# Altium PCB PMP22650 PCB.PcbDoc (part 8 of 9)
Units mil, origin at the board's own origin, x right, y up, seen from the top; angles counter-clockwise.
Board outline 11311 x 5233 mil, 8 copper layers (Layer 1, Layer 2, Layer 3, Layer 4, Layer 5, Layer 6, Layer 7, Layer 8), stack 88.6 mil thick; 633 components, 410 nets, 2503 pads, 1993 vias.
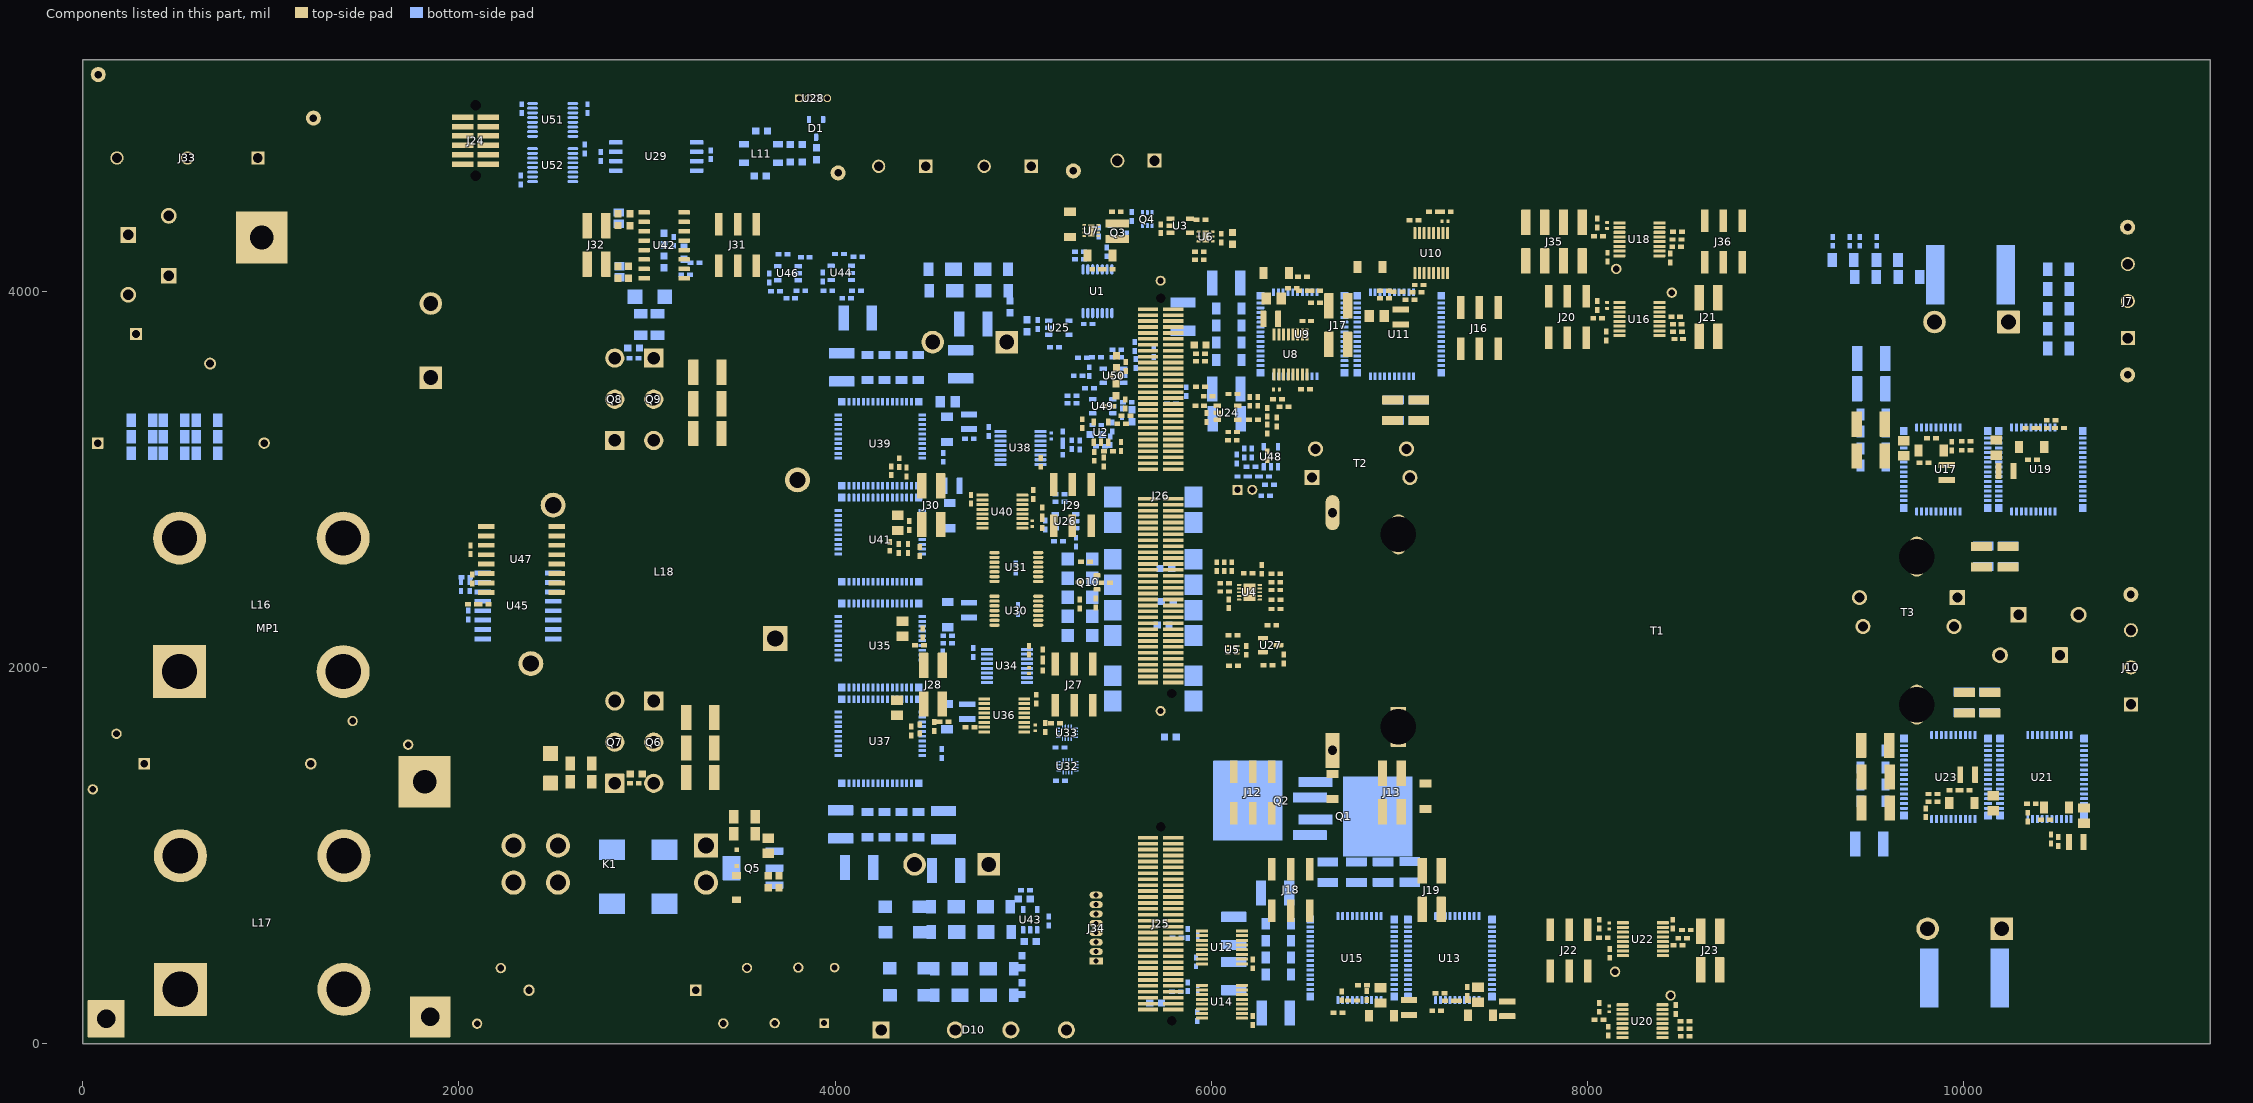
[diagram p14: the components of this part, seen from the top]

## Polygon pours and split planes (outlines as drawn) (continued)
NetL3_2 on Layer 8 "NONET_L-01_P-001" (solid, remove dead copper, pour order 249): 6232.27,4022 6282.27,4022 6282.27,3958.6 6232.27,3958.6
PGND on Layer 8 "NONET_L-01_P-001" (solid, remove dead copper, pour order 251): 5782,3997.6 5925,3997.6 5925,3912.6 5782,3912.6
NetL5_2 on Layer 8 "NONET_L-01_P-001" (solid, remove dead copper, pour order 255): 7469,203 7518.27,203 7518.27,274.6 7469,274.6
ISO_12V_L_B on Layer 8 "NONET_L-01_P-001" (solid, remove dead copper, pour order 16): 7375,135.4 7410.85,135.4 7410.85,185 7375,185
VNEG_L_B on Layer 8 "NONET_L-01_P-001" (solid, remove dead copper, pour order 17): 7446,324.6 7446,281.6 7513.27,281.6 7513.27,324.6 7468.27,324.6
NetL6_2 on Layer 8 "NONET_L-01_P-001" (solid, remove dead copper, pour order 256): 6938.27,274.6 6938.27,201 6993.27,201 6993.27,274.6
VNEG_H_B on Layer 8 "NONET_L-01_P-001" (solid, remove dead copper, pour order 257): 6927,324.6 6993.27,324.6 6993.27,281.6 6927,281.6
VNEG_H_PFC_1 on Layer 8 "NONET_L-01_P-001" (solid, remove dead copper, pour order 263): 4373.27,1852.6 4373.27,1792.6 4413.27,1792.6 4413.27,1852.6
ISO_12V_H_PFC_1 on Layer 8 "NONET_L-01_P-001" (solid, remove dead copper, pour order 266): 4563.27,1697.6 4648.27,1697.6 4648.27,1652.6 4563.27,1652.6
VNEG_H_PFC_1 on Layer 8 "NONET_L-01_P-001" (solid, remove dead copper, pour order 15): 4373.27,1852.6 4373.27,1787.6 4413.27,1787.6 4413.27,1852.6
VNEG_L_PFC_1 on Layer 8 "NONET_L-01_P-001" (solid, remove dead copper, pour order 269): 4373.27,2367.6 4373.27,2292.6 4413.27,2292.6 4413.27,2367.6
NetL12_2 on Layer 8 "NONET_L-01_P-001" (solid, remove dead copper, pour order 270): 4423.27,2362.6 4423.27,2302.6 4468.27,2302.6 4468.27,2362.6
NetL12_2 on Layer 8 "NONET_L-01_P-001" (solid, remove dead copper, pour order 276): 4668.27,2302.6 4753.27,2302.6 4753.27,2252.6 4668.27,2252.6
ISO_12V_L_PFC_1 on Layer 8 "NONET_L-01_P-001" (solid, remove dead copper, pour order 278): 4568.27,2257.6 4628.27,2257.6 4628.27,2192.6 4568.27,2192.6
NetL14_2 on Layer 8 "NONET_L-01_P-001" (solid, remove dead copper, pour order 280): 4686.27,3302.6 4668.27,3284.6 4668.27,3252.6 4754.27,3252.6 4754.27,3283.6 4735.27,3302.6
NetL14_2 on Layer 8 "NONET_L-01_P-001" (solid, remove dead copper, pour order 281): 4423.27,3437.6 4498.27,3437.6 4498.27,3392.6 4423.27,3392.6
VNEG_L_PFC_2 on Layer 8 "NONET_L-01_P-001" (solid, remove dead copper, pour order 283): 4373.27,3437.6 4373.27,3362.6 4413.27,3362.6 4413.27,3437.6
VNEG_L_PFC_2 on Layer 8 "NONET_L-01_P-001" (solid, remove dead copper, pour order 284): 4513.27,3447.6 4583.27,3447.6 4583.27,3382.6 4513.27,3382.6
IPRI_SENSE on Layer 8 "NONET_L-01_P-001" (solid, remove dead copper, pour order 289): 3978.27,3927.6 4073.27,3927.6 4073.27,3792.6 3978.27,3792.6
AC_N on Layer 8 "NONET_L-01_P-001" (solid, remove dead copper, pour order 290): 2810.27,4181 2895.27,4181 2895.27,4109.6 2810.27,4109.6
ISO_12V_H_RECT on Layer 8 "NONET_L-01_P-001" (solid, remove dead copper, pour order 291): 2815.27,4099.6 2895.27,4099.6 2895.27,4034.6 2815.27,4034.6
IPRI_SENSE on Layer 8 "NONET_L-01_P-001" (solid, remove dead copper, pour order 294): 2920,4444.6 2920,4394.6 2815.27,4394.6 2815.27,4444.6
PGND on Layer 8 "NONET_L-01_P-001" (solid, remove dead copper, pour order 299): 1973.27,2497.6 2023.27,2497.6 2023.27,2442.6 1973.27,2442.6
ISO_ETAS_GND on Layer 8 "NONET_L-01_P-001" (solid, remove dead copper, pour order 306): 2308.27,4547.6 2308.27,4592.6 2423.27,4592.6 2423.27,4547.6
ISO_3.3V on Layer 8 "NONET_L-01_P-001" (solid, remove dead copper, pour order 309): 2423.27,4832.6 2358.27,4832.6 2354.53,4971.16 2263.27,4971.16 2263.27,4832.6 2218.27,4787.6 2218.27,4757.6 2298.27,4677.6 2298.27,4602.6 2423.27,4602.6 2423.27,4622.6 2363.27,4622.6 2358.27,4627.6 2358.27,4747.6 2423.27,4747.6
ISO_ETAS_GND on Layer 8 "NONET_L-01_P-001" (solid, remove dead copper, pour order 310): 2308.27,4969.61 2308.27,5042.6 2423.27,5042.6 2423.27,4987.6 2359.15,4987.6 2359.15,4969.61
3V3_PRI on Layer 8 "NONET_L-01_P-001" (solid, remove dead copper, pour order 311): 2568.27,4832.6 2638.27,4832.6 2638.27,4937.6 2673.27,4972.6 2733.27,4972.6 2733.27,4762.6 2638.27,4762.6 2628.27,4752.6 2568.27,4752.6
PGND on Layer 8 "NONET_L-01_P-001" (solid, remove dead copper, pour order 313): 22 vertices, not listed, extent 2568.27,4542.6 2873.27,4817.6
3V3_PRI on Layer 8 "NONET_L-01_P-001" (solid, remove dead copper, pour order 324): 2798.27,4662.6 2873.27,4662.6 2873.27,4607.6 2868.27,4602.6 2798.27,4602.6
PGND on Layer 8 "NONET_L-01_P-001" (solid, remove dead copper, pour order 349): 2573.27,5042.6 2703.27,5042.6 2703.27,4982.6 2648.27,4982.6 2638.27,4992.6 2573.27,4992.6
5V_H_B on Layer 1 "NONET_L-01_P-001" (solid, pour order 522): 6107,276 6109,274 6189,274 6194,279 6194,295 6133,295 6128,300 6107,300
SW_B on Layer 1 "Layer 1-HS_GND_B" (solid, remove dead copper, pour order 454): 6132.25,153 6198.4,150.83 6259.49,78 7098,78 7098,250 7098,340 6551.81,337.61 6549.85,201.24 6498,153 6297.71,153 6250.62,192 6250.62,337.61 6132.25,340
5V_H_B on Layer 1 "NONET_L-01_P-001" (solid, pour order 521): 6170,145 6171,144 6194,144 6222,116 6222,83 6173,83 6152,104 6152,145
DCLINK on Layer 1 "NONET_L-01_P-001" (solid, pour order 514): 6035,113 6072,113 6072,92 6035,92
PGND on Layer 1 "NONET_L-01_P-001" (solid, pour order 513): 6121,623 6122,624 6255,624 6255,434 6121.99,434
SW_A on Layer 1 "NONET_L-01_P-001" (solid, pour order 400): 23 vertices, not listed, extent 6683,3651 7289,4139
PGND on Layer 1 "NONET_L-01_P-001" (solid, pour order 462): 7194,822 7490.93,822 7490.93,372.24 7639,228 7639,142 7575,78 7156.49,78 7156.49,385 6546,385 6546,632 7194,632
SW_C on Layer 1 "NONET_L-01_P-001" (solid, pour order 504): 10137,3160 10137,3105 10220.79,3105 10230,3084 10230,2999 10289,2999 10294,3004 10294,3126 10260,3160
5V_H_D on Layer 1 "NONET_L-01_P-001" (solid, pour order 434): 8584,750 8467,633 8369,633.78 8369,599 8487,599 8584,696 9428,696 9863,1131 9863,1317 9731,1317 9731,1090 9391,750
IPRI_SENSE on Layer 1 "NONET_L-01_P-001" (solid, remove dead copper, pour order 186): 4496.59,3118.88 4496.59,2896.41 4477.88,2877.7 4390.56,2877.7 4299.27,2968.98 4248.18,2968.98 4248.18,3013.16 4275.61,3040.6 4400.92,3040.6 4400.92,3045.84 4437.98,3082.91 4437.98,3118.88
TTPLPFC_SW1 on Layer 1 "Layer 1-HS_GND_PFC_1" (solid, pour order 465): 4425,1498 4826,1498 4826,1666 4726,1666 4713,1679 4713,1699 4474,1699 4474,1727.27 4440.13,1727.27 4413.83,1777.6 4295,1777.6 4295,1628
SGND on Layer 1 "NONET_L-01_P-001" (solid, pour order 425): 9841,3258 9869,3258 9869,3236 9897,3236 9920,3213 9920,3171 9951,3171 9951,3123 9951,3068 9886,3068 9832,3122 9832,3208.4
3V3_PRI on Layer 1 "NONET_L-01_P-001" (solid, remove dead copper, pour order 175): 25 vertices, not listed, extent 5990.27,3388.93 6540,4307.91
VNEG_H_PFC_2 on Layer 1 "NONET_L-01_P-001" (solid, remove dead copper, pour order 287): 4297,2848.6 4297,2780 4360,2780 4406,2826 4406,2848.6
TTPLPFC_SW2 on Layer 1 "NONET_L-01_P-001" (solid, pour order 403): 4299,2757 4404,2757 4404,2691 4299,2691
ISO_12V_H_PFC_2 on Layer 1 "NONET_L-01_P-001" (solid, remove dead copper, pour order 292): 4436,2827.6 4483.27,2827.6 4513.27,2797.6 4513.27,2757.6 4483.27,2727.6 4483.27,2692.6 4436,2692.6
LC_GATE on Layer 1 "NONET_L-01_P-001" (solid, remove dead copper, pour order 114): 7031.27,1520 6401.94,1520 6401.94,1114 6586.74,1114 6586.74,1164.6 6487.28,1164.6 6487.28,1318.71 6512.5,1339 6698,1339 7031.27,1339
3V3_PRI on Layer 1 "NONET_L-01_P-001" (solid, remove dead copper, pour order 217): 6344,2524.47 6189,2524.47 6189,2492 6158.36,2475.16 6158.36,2430.28 6140.71,2430.28 6120,2450.99 6120,2512.56 6096.99,2535.57 5980.2,2535.57 5980.2,3167.7 6344,3167.7
5V_L_D on Layer 1 "NONET_L-01_P-001" (solid, pour order 436): 8506,253 8840,253 8966,379 9421,379 9825,783 10009,783 10368,1142 10448,1142 10448,998 10136,686 9791,686 9370,265 8962,265 8830,133 8506,135.01
DCLINK on Layer 1 "NONET_L-01_P-001" (solid, remove dead copper, pour order 329): 3175.66,3642.6 3310,3642.6 3310,3177.6 3181.86,3177.6 3088.18,3287.6 2765.55,3287.6 2765.55,3571.6 3093.64,3571.6
PGND on Layer 1 "NONET_L-01_P-001" (solid, remove dead copper, pour order 166): 5952.26,4230.6 5952.26,4150.6 5990.27,4150.6 5990.27,4260.31 5989.27,4261.31 5990.27,4262.31 5990.27,4303.25 6020.1,4303.25 6032.68,4290.67 6140.59,4290.67 7052,4290.67 7135,4290.67 7135,4431 5952.26,4431
TTPLPFC_SW1 on Layer 1 "NONET_L-01_P-001" (solid, pour order 451): 4543,1875 4704,1875 4762,1817 4824,1817 4824,1802 4762,1802 4697,1737 4544,1737
ISO_12V_H_PFC_1 on Layer 1 "NONET_L-01_P-001" (solid, remove dead copper, pour order 188): 4443,1883.01 4518.26,1883.01 4518.26,1751.5 4443,1752.51
TTPLPFC_SW2 on Layer 1 "NONET_L-01_P-001" (solid, remove dead copper, pour order 293): 4528.27,2666 4528.27,2707.6 4528.27,2762.6 4528.27,2868 4688.67,2868 4723.02,2902.35 4812,2902.35 4812,2666
5V_PRI on Layer 1 "NONET_L-01_P-001" (solid, remove dead copper, pour order 147): 5424.27,4324.44 5424.27,4147.6 5944.27,4147.6 5944.27,4324.44
NetL4_2 on Layer 1 "NONET_L-01_P-001" (solid, pour order 1): 6963,3923 6963,3884 6964,3884 6976,3872 7041,3872 7054,3885 7054,3923
5V_H_A on Layer 1 "NONET_L-01_P-001" (solid, pour order 383): 7019,4133 7095,4133 7095,3979 7095,3940 7019,3940 7019,3955
SW_A on Layer 1 "NONET_L-01_P-001" (solid, pour order 396): 6746,4169 6746,4053 6879,4053.01 6879,4169
TTPLPFC_SW2 on Layer 1 "NONET_L-01_P-001" (solid, remove dead copper, pour order 181): 4375.42,2628 4398.92,2628 4412.66,2616.32 4473,2616.32 4473,2579 4375.42,2579
PGND on Layer 1 "NONET_L-01_P-001" (solid, remove dead copper, pour order 221): 5285.15,2812 5139,2812 5139,2760.83 4958,2760.83 4958,2673.07 5287.06,2673.07
3V3_PRI on Layer 1 "NONET_L-01_P-001" (solid, pour order 494): 4962,2958 5066,2958 5066,2917 5057,2908 4962,2908
ISO_12V_L_PFC_2 on Layer 1 "NONET_L-01_P-001" (solid, remove dead copper, pour order 182): 4630.47,3147.91 4525.28,3030.41 4525.28,2891.46 4586.55,2891.46 4790.5,3095.64 4790.5,3147.91
NetL8_2 on Layer 1 "NONET_L-01_P-001" (solid, pour order 484): 10169,3088 10222,3088 10222,3002 10169,3002
SW_C on Layer 1 "NONET_L-01_P-001" (solid, pour order 428): 10352,3307.96 10378,3307.96 10416.26,3264 10506.92,3264 10507.5,3286.53 10586,3286.53 10586,3229.73 10557.21,3230.43 10532,3211.35 10532,3139 10352,3139
VNEG_H_C on Layer 1 "NONET_L-01_P-001" (solid, pour order 2): 10135,3243 10232,3243 10232,3184 10135,3184
NetL3_2 on Layer 1 "NONET_L-01_P-001" (solid, pour order 29): 6295,3816 6295,3898 6262,3931 6262,3999 6279,3999 6283,4003 6283,4018 6231,4018 6231,3964 6244,3951 6244,3804 6291,3804 6293,3802
ISO_12V_L_D on Layer 1 "NONET_L-01_P-001" (solid, pour order 413): 20 vertices, not listed, extent 8572,256 10568,1490
SGND on Layer 1 "NONET_L-01_P-001" (solid, pour order 35): 10405,1277 10486,1277 10492,1271 10492,1179 10405,1179
SW_D on Layer 1 "NONET_L-01_P-001" (solid, pour order 409): 9733,1490 10196,1490 10196,1261 10196,1148 10045,1148 10044,1149 10044,1242 10036,1250 10036,1315 10027,1324 9733,1324
ISO_12V_H_D on Layer 1 "NONET_L-01_P-001" (solid, pour order 411): 8731,526 8731,690 9428,690 9868,1130 9868,1319.85 10040,1315.55 10040,1156 9410,526
PGND on Layer 1 "NONET_L-01_P-001" (solid, remove dead copper, pour order 212): 20 vertices, not listed, extent 5888,3326 6113.43,3745.96
ISO_12V_H_RECT on Layer 1 "NONET_L-01_P-001" (solid, remove dead copper, pour order 204): 2655,4216 2712.76,4216 2712.76,4083.24 2732.89,4063.11 2795.11,4063.11 2824.53,4092.53 3019,4092.53 3019,4041.78 2939.82,3962.6 2655,3962.6
AC_N on Layer 1 "NONET_L-01_P-001" (solid, remove dead copper, pour order 196): 2754.24,4214.8 2899.47,4214.8 2930.67,4183.6 2986.27,4183.6 2986.27,4160.6 2983.27,4163.6 2920.34,4163.6 2901.27,4144.52 2901.27,4112.6 2818.6,4112.6 2780,4074 2755.28,4074
IPRI_SENSE on Layer 1 "NONET_L-01_P-001" (solid, remove dead copper, pour order 326): 3352,3642.6 4454.27,3642.6 4454.27,3348 4406.57,3323.2 4406.57,3177.6 3352,3177.6
SGND on Layer 1 "NONET_L-01_P-001" (solid, remove dead copper, pour order 481): 8363,3954 8533,3954 8533,3651 8363,3651
SW_C on Layer 1 "NONET_L-01_P-001" (solid, pour order 479): 8497,4008.6 8373.5,4132.1 8373.5,4447 8587.18,4447 8587.18,4079.82 8642,4025 8642,3898 8497,3898
ISO_12V_H_C on Layer 1 "NONET_L-01_P-001" (solid, pour order 480): 8668,4043 9556,4043 9696,3901 9696,3824 9833.89,3679.8 9916.22,3677.63 10059,3540 10173,3540 10295,3418 10295,3302 10115,3302 10115,3350 9564,3901 8668,3901
VBATT_F on Layer 1 "NONET_L-01_P-001" (solid, remove dead copper, pour order 97): 9767.05,4318.67 9968.27,4318.67 9968.27,3777 9812.35,3781.65 9767.05,3826.95
SGND on Layer 1 "NONET_L-01_P-001" (solid, pour order 476): 8524,3760 8484,3760 8484,3736 8524,3736
ISO_12V_L_C on Layer 1 "NONET_L-01_P-001" (solid, remove dead copper, pour order 381): 18 vertices, not listed, extent 8546,3122 9810.33,3833.55
SGND on Layer 1 "NONET_L-01_P-001" (solid, remove dead copper, pour order 379): 8639,3841 8725,3841 8725,3674 8639,3674
PGND on Layer 1 "NONET_L-01_P-001" (solid, pour order 401): 6253,4146.71 6253,4066.42 6304,4031 6339,3996 6339,3913.82 6320.32,3892.85 6320.32,3737 6347,3737 6347,3824 6657,3824 6657,4023 6368,4023 6368,4148.96
ISO_12V_L_A on Layer 1 "NONET_L-01_P-001" (solid, pour order 466): 6747,3991 6673,3991 6673,3855 6671,3853 6673,3851 6749,3851
VNEG_L_B on Layer 1 "NONET_L-01_P-001" (solid, pour order 464): 7382,329 7474,329 7475,330 7476,329 7476,275 7383,275 7382,276
NetL5_2 on Layer 1 "NONET_L-01_P-001" (solid, pour order 37): 7620,251 7619,250 7462,250 7462,200 7466,196 7623,196
ISO_12V_H_B on Layer 1 "NONET_L-01_P-001" (solid, pour order 461): 6815,181 6870,181 6885,166 6885,119 6816,119 6815,118
VNEG_H_B on Layer 1 "NONET_L-01_P-001" (solid, pour order 459): 6867,330 6869,331 6953,331 6953,272 6951,270 6867,270
NetL6_2 on Layer 1 "NONET_L-01_P-001" (solid, pour order 453): 7094.77,252 6974,252 6943,221 6943,206 6999,206 7095.82,206
PGND on Layer 1 "NONET_L-01_P-001" (solid, pour order 449): 4973,1824 5049,1824 5059,1834 5113,1834 5141,1862 5193,1862 5193,1740 5189,1736 5154,1736 5098,1792 5051,1792 5041,1802 4973,1802
PGND on Layer 1 "NONET_L-01_P-001" (solid, pour order 448): 4970,1671 4972,1673 5129,1673 5134,1668 5134,1619 5074,1559 4992,1559 4992,1617 4970,1639
3V3_PRI on Layer 1 "NONET_L-01_P-001" (solid, pour order 447): 5080.75,1932 5051,1932 4974,1855 4974,1827 5039,1827 5051,1839 5082,1839 5085,1842 5085,1926.33
IPRI_SENSE on Layer 1 "NONET_L-01_P-001" (solid, pour order 445): 2821,4443 3018,4443 3026,4435 3026,4402 2946,4402 2929,4385 2820,4385
PGND on Layer 1 "NONET_L-01_P-001" (solid, pour order 442): 3278,4303 3123,4303 3123,4211 3131,4203 3278,4203
ISO_12V_L_B on Layer 1 "NONET_L-01_P-001" (solid, pour order 441): 7098,822 7178,822 7178,648 7093,648 7093,822
3V3_PRI on Layer 1 "NONET_L-01_P-001" (solid, pour order 440): 2055,2474 2056,2475 2216,2475 2216,2316 2218,2314 2138,2314 2138,2360 2070,2428 2055,2428
SGND on Layer 1 "NONET_L-01_P-001" (solid, remove dead copper, pour order 96): 9518.27,3681.6 9637,3681.6 9637,3021.6 9518.27,3021.6
5V_PRI on Layer 1 "NONET_L-01_P-001" (solid, pour order 439): 5908,1241 5959,1292 6148,1292 6148,1074 6360,761 6360,649 6299.65,649 6011.55,903.86 5908,1074
5V_PRI on Layer 1 "NONET_L-01_P-001" (solid, pour order 437): 7777.5,452 7850.5,452 7851.5,451 7851.5,325 7777.5,325
VBATT on Layer 1 "NONET_L-01_P-001" (solid, remove dead copper, pour order 42): 10452.27,1751.1 11037.61,1751.1 11037.61,2465.6 10452.27,2465.6
BATT_RTN on Layer 1 "NONET_L-01_P-001" (solid, remove dead copper, pour order 50): 10507.83,3819.86 10759.21,3643.77 11093.17,3644.63 11093.17,4405.2 10784.85,4405.2 10784.85,4184.41 10677.85,4071.16 10507.83,4071.16
SGND on Layer 1 "NONET_L-01_P-001" (solid, remove dead copper, pour order 51): 10160.27,4280.6 10413,4280.6 10413,3621 10160.27,3621
SW_D_RES on Layer 1 "NONET_L-01_P-001" (solid, remove dead copper, pour order 70): 9705.01,1692.61 9705.01,2012 10221.72,2012 10221.72,1810.36 9925.91,1810.36 9783.64,1692.61
SW_D on Layer 1 "NONET_L-01_P-001" (solid, remove dead copper, pour order 80): 9911.41,1677.29 9911.41,1795.13 10221.72,1795.13 10221.72,1677.93
SW_C on Layer 1 "NONET_L-01_P-001" (solid, remove dead copper, pour order 81): 10323.71,2732.56 10323.71,2616.6 10013.9,2616.6 10013.9,2732.56
SW_C_XFMR on Layer 1 "NONET_L-01_P-001" (solid, remove dead copper, pour order 82): 9802.32,2446 9534,2446 9534,2744 9801.72,2744
PGND on Layer 1 "NONET_L-01_P-001" (solid, remove dead copper, pour order 100): 6162.57,1434.61 6259.56,1434.61 6258.79,1074 6331.42,1052.6 6620.27,1052.6 6620.27,866 6303.18,866 6162.57,1074
SW_A_RES on Layer 1 "NONET_L-01_P-001" (solid, remove dead copper, pour order 108): 6706.27,3387.6 7170.75,3387.6 7170.75,3231.6 6706.27,3231.6
SW_A on Layer 1 "NONET_L-01_P-001" (solid, remove dead copper, pour order 109): 6848.27,3502.6 7182.64,3502.6 7182.64,3402.6 6848.27,3402.6
SW_A_XFMR on Layer 1 "NONET_L-01_P-001" (solid, remove dead copper, pour order 113): 6566,2946 7065.68,2946 7065.68,2590.97 6566,2590.97
LC_GND on Layer 1 "NONET_L-01_P-001" (solid, remove dead copper, pour order 115): 7031.27,1319 7031.27,1153 6613,1153 6593,1173 6504.61,1173 6504.61,1319 6660.77,1319
12V_PRI on Layer 1 "NONET_L-01_P-001" (solid, remove dead copper, pour order 214): 5682.51,1280.37 5682.51,1664 6375.8,1664 6375.8,1155 6279,1155 6279,1512 5947.84,1512 5761.27,1325.42 5761.27,1278.84
SW_C_RES on Layer 1 "NONET_L-01_P-001" (solid, remove dead copper, pour order 424): 10322.71,2592 10322.71,2455.6 9915,2455.6 9915,2592
SW_D on Layer 1 "NONET_L-01_P-001" (solid, remove dead copper, pour order 246): 8575,691 8668,691 8668,531 8575,531
SGND on Layer 1 "NONET_L-01_P-001" (solid, pour order 427): 9645.95,3168.97 9735.95,3168.97 9735.95,3116.97 9728.95,3109.97 9644.93,3109.97
NetL7_2 on Layer 1 "NONET_L-01_P-001" (solid, pour order 426): 9866.5,2979.5 9866.5,3043.5 9930.5,3043.5 9957,3017 9957,2979.5
PGND on Layer 1 "NONET_L-01_P-001" (solid, remove dead copper, pour order 107): 7825.23,4253.56 7796.27,4224.6 7796.27,4036.6 7727.27,4036.6 7634.27,3943.6 7634.27,3788.1 7294,3788.1 7294,3522.6 7916.33,3522.6 8007,3613.26 8007,4253.56
NetL10_2 on Layer 1 "NONET_L-01_P-001" (solid, pour order 417): 9966,1475 10009,1475 10011,1473 10009,1471 10009,1384 9968,1384 9966,1386
ISO_12V_H_D on Layer 1 "NONET_L-01_P-001" (solid, pour order 410): 9900,1314 10032,1314 10032,1251 10046,1237 10046,1218 10026,1218 10025,1217 10020,1222 10020,1236 10008,1248 9900,1248
VNEG_H_D on Layer 1 "VNET_H_D_SHAPE_1" (solid, pour order 38): 10086,1245 10087,1244 10109,1244 10109,1255 10132,1278 10192,1278 10192,1344 10188,1348 10106,1348 10106,1308 10086,1288
NetL9_2 on Layer 1 "NONET_L-01_P-001" (solid, pour order 408): 10615,1140 10615,1028 10662,1028 10665,1031 10665,1139
SGND on Layer 1 "NONET_L-01_P-001" (solid, pour order 407): 10526,1174 10529,1177 10602,1177 10602,1043 10580,1021 10534,1021 10526,1029 10484.51,1030.55 10484.51,1067.5 10526,1086.37
VNEG_L_D on Layer 1 "NONET_L-01_P-001" (solid, remove dead copper, pour order 239): 10670,1288.56 10584.99,1288.56 10584.99,1211.46 10670,1211.46
3V3_PRI on Layer 1 "NONET_L-01_P-001" (solid, pour order 406): 3120.74,4190.5 3230,4190.5 3230,4147.5 3222,4139.5 3121.74,4139.5
ISO_12V_L_A on Layer 1 "NONET_L-01_P-001" (solid, pour order 402): 6393,4203 6372,4182 6372,4047 6402,4047 6453,4098 6453,4202
ISO_12V_H_A on Layer 1 "NONET_L-01_P-001" (solid, pour order 399): 6887.54,4162 6992,4162 7013,4141 7013,4045 6890.09,4045
IPRI_SENSE on Layer 1 "NONET_L-01_P-001" (solid, remove dead copper, pour order 382): 3969.09,1135 4710,1135 4710,642 5315,37 4777,37 4108.09,705.91 3969.09,705.91
ISO_12V_H_D on Layer 1 "NONET_L-01_P-001" (solid, remove dead copper, pour order 247): 8674,687 8757,687 8757,529 8674,529
PGND on Layer 1 "NONET_L-01_P-001" (solid, remove dead copper, pour order 180): 2180.27,2634.6 2180.27,2773.6 2179.27,2774.6 2178.27,2773.6 1875,2773.6 1875,2090 2132,2090 2132,2358.38 2070,2358.38 2070,2314 2028,2314 2028,2634.52
12V_SW on Layer 1 "NONET_L-01_P-001" (solid, remove dead copper, pour order 105): 6389.43,770 6588.57,770 6588.57,644.62 6389.43,644.62
SW_B on Layer 1 "NONET_L-01_P-001" (solid, remove dead copper, pour order 275): 7091.2,989 7178.8,989 7178.8,849.09 7091.2,849.09
ISO_12V_H_B on Layer 1 "NONET_L-01_P-001" (solid, remove dead copper, pour order 277): 7198.68,990 7273,990 7273,846.62 7198.68,846.62
VBATT_F on Layer 1 "NONET_L-01_P-001" (solid, remove dead copper, pour order 83): 9331.17,3703.9 9484,3703.9 9484,3033.6 9331.17,3033.6
ISO_12V_H_A on Layer 1 "NONET_L-01_P-001" (solid, remove dead copper, pour order 378): 6648,3708 6598,3708 6597,3707 6598,3706 6598,3622 6648,3622
DCLINK on Layer 1 "NONET_L-01_P-001" (solid, remove dead copper, pour order 330): 3295,1822.6 3779,1822.6 3779,2524 4389,2524 4389,2343 4256,2343 4256,1596 4441.27,1410.73 4441.27,1320.6 3295,1320.6
12V_SW on Layer 1 "NONET_L-01_P-001" (solid, remove dead copper, pour order 41): 7865.5,3818 8010.5,3818 8010.5,3690.67 7865.5,3690.67
SGND on Layer 1 "NONET_L-01_P-001" (solid, remove dead copper, pour order 52): 9373.76,1661.6 9474.27,1661.6 9474.27,1141.6 9374.82,1141.6
VBATT_F on Layer 1 "NONET_L-01_P-001" (solid, remove dead copper, pour order 53): 9524.27,1710.6 9671,1710.6 9671,1132 9524.27,1132
AC_L_Sense_2 on Layer 1 "NONET_L-01_P-001" (solid, remove dead copper, pour order 98): 2276.73,2949.6 2553.27,2949.6 2553.27,2575.6 2276.73,2575.6
AC_L on Layer 1 "NONET_L-01_P-001" (solid, remove dead copper, pour order 99): 2277.27,2565.82 2553.27,2565.82 2553.27,2301.6 2277.27,2301.6
PGND on Layer 1 "NONET_L-01_P-001" (solid, remove dead copper, pour order 106): 7773,707.29 8028,707.29 8219.14,653.23 8219.14,632.62 8028,632.62 8028,537 7773,537
12V_PRI on Layer 1 "NONET_L-01_P-001" (solid, remove dead copper, pour order 153): 5336.27,4339.6 5329.77,4346.09 5210.87,4346.09 5210.87,4217.6 5297.27,4217.6 5297.27,4302.79 5332.54,4302.79 5337.27,4307.52
PGND on Layer 1 "NONET_L-01_P-001" (solid, remove dead copper, pour order 164): 18 vertices, not listed, extent 5143.27,4097.2 5398.27,4449.52
12V_SW on Layer 1 "NONET_L-01_P-001" (solid, remove dead copper, pour order 176): 7301,3984.56 7475,3984.56 7475,3796.15 7301,3796.15
12V_SW on Layer 1 "NONET_L-01_P-001" (solid, remove dead copper, pour order 178): 7872.26,468 8031.74,468 8031.74,323.2 7872.26,323.2
VNEG_H_PFC_1 on Layer 1 "NONET_L-01_P-001" (solid, remove dead copper, pour order 187): 4302.71,1857.6 4413.83,1857.6 4413.83,1790.95 4412.36,1789.48 4302.71,1789.48
IPRI_SENSE on Layer 1 "NONET_L-01_P-001" (solid, remove dead copper, pour order 195): 4314.85,2195.65 4314.85,1947.75 4499,1946.32 4499,2067.76 4435.6,2131.16 4444.97,2140.54 4477.8,2140.54 4477.88,2195.65 4394.85,2195.65
ISO_12V_L_RECT on Layer 1 "NONET_L-01_P-001" (solid, remove dead copper, pour order 203): 2755,4418 2806,4418 2818.42,4390.91 2840.39,4374.6 2908.06,4374.6 2944.06,4338.6 3014,4338.6 3014,4309.5 2973.15,4309.5 2947,4282 2755,4282
PGND on Layer 1 "NONET_L-01_P-001" (solid, remove dead copper, pour order 205): 3620.95,857.75 3728.81,857.75 3728.81,804.13 3678.09,753.42 3620.95,753.42
TTPLPFC_INRUSH_RELAY on Layer 1 "NONET_L-01_P-001" (solid, remove dead copper, pour order 206): 3740.27,998 3740.27,868.7 3605.37,868.7 3602.54,871.53 3602.54,962.08 3680.08,962.08 3716,998
PGND on Layer 1 "NONET_L-01_P-001" (solid, remove dead copper, pour order 209): 3559.77,1046 3684.27,1046 3684.27,981.6 3559.77,981.6
PGND on Layer 1 "NONET_L-01_P-001" (solid, remove dead copper, pour order 218): 6340.11,3455.14 6334.31,3460.94 6169.72,3460.94 6169.72,3422.06 6168.01,3420.35 6183.11,3405.25 6340.11,3405.25
PGND on Layer 1 "NONET_L-01_P-001" (solid, remove dead copper, pour order 219): 29 vertices, not listed, extent 5897.35,2048.13 6395.7,2513.27
5V_PRI on Layer 1 "NONET_L-01_P-001" (solid, remove dead copper, pour order 220): 6318.65,2237.1 6273.36,2237.1 6273.36,2231.72 6217.97,2176.33 6172.24,2176.33 6172.24,2145.2 6176.32,2141.12 6318.65,2141.12
VNEG_L_C on Layer 1 "NONET_L-01_P-001" (solid, remove dead copper, pour order 223): 9692.61,3231.38 9728.95,3231.38 9728.95,3194.06 9713.14,3178.25 9652.46,3178.25 9652.46,3227.57 9656.27,3231.38
SGND on Layer 1 "NONET_L-01_P-001" (solid, remove dead copper, pour order 264): 8679,464 8767,464 8767,325 8679,325
3V3_PRI on Layer 1 "NONET_L-01_P-001" (solid, remove dead copper, pour order 272): 7925,4437 8003.27,4437 8003.27,4292.6 7925,4292.6
5V_PRI on Layer 1 "NONET_L-01_P-001" (solid, remove dead copper, pour order 274): 7500,3984.56 7575,3984.56 7575,3796.32 7500,3796.32
5V_PRI on Layer 1 "NONET_L-01_P-001" (solid, remove dead copper, pour order 36): 7762.81,3835.13 7852.81,3835.13 7852.81,3668.61 7762.81,3668.61
5V_PRI on Layer 1 "NONET_L-01_P-001" (solid, remove dead copper, pour order 285): 5391,2102 5391,1992.6 5353.27,1992.6 5348.27,1997.6 5348.27,2102
VNEG_L_PFC_1 on Layer 1 "NONET_L-01_P-001" (solid, remove dead copper, pour order 286): 4418.27,2322.6 4418.27,2247.6 4393.27,2222.6 4328.27,2222.6 4328.27,2272.6 4368.27,2272.6 4368.27,2322.6
5V_PRI on Layer 1 "NONET_L-01_P-001" (solid, remove dead copper, pour order 296): 5303.27,3361.6 5303.27,3302.6 5398.27,3302.6 5398.27,3361.6
IPRI_SENSE on Layer 1 "NONET_L-01_P-001" (solid, remove dead copper, pour order 297): 2601,4421 2708,4421 2708,4276 2601,4276
12V_SW on Layer 1 "NONET_L-01_P-001" (solid, remove dead copper, pour order 314): 3357.5,4417 3522.5,4417 3522.5,4297 3357.5,4297
PGND on Layer 1 "NONET_L-01_P-001" (solid, remove dead copper, pour order 325): 3358,4206 3628,4206 3628,4076 3358,4076
IPRI_SENSE on Layer 1 "NONET_L-01_P-001" (solid, remove dead copper, pour order 340): 2779.62,1882.6 3273,1882.6 3273,1322.6 2941.27,1322.6 2941.27,1556.94 2779.62,1718.59
3V3_PRI on Layer 1 "NONET_L-01_P-001" (solid, remove dead copper, pour order 343): 3130.27,4442.6 3229,4442.6 3229,4392.6 3130.27,4392.6
ISO_12V_L_PFC_1 on Layer 1 "NONET_L-01_P-001" (solid, remove dead copper, pour order 344): 4567.27,2263.6 4637.27,2263.6 4637.27,2189.6 4631.27,2183.6 4566.27,2183.6
3V3_PRI on Layer 1 "NONET_L-01_P-001" (solid, remove dead copper, pour order 355): 7043.27,4345.6 7091.27,4345.6 7091.27,4262.6 7043.27,4262.6
VNEG_L_A on Layer 1 "NONET_L-01_P-001" (solid, remove dead copper, pour order 377): 6267.27,3994.6 6267.27,3923.6 6286.27,3904.6 6325.27,3904.6 6325.27,3994.6
PGND on Layer 3 "NONET_L-01_P-001" (solid, remove dead copper, pour order 199): 1753.83,4445.6 1752.72,1217.32 2608.27,1217.32 2608.27,-1.4 8216.27,-1.4 8216.27,4445.6 2949.66,4445.6 2946.88,5059.76 2553.27,5059.76 2553.27,4445.6
SW_B on Layer 3 "NONET_L-01_P-001" (solid, remove dead copper, pour order 57): 6801.27,397.6 6695.48,397.6 6644.31,337.6 6134.61,337.6 6134.61,101 7117,101 7117,397.6
DCLINK on Layer 3 "NONET_L-01_P-001" (solid, pour order 516): 6035.8,113 6072.8,113 6072.8,92 6035.8,92
AC_N_Re on Layer 3 "NONET_L-01_P-001" (solid, remove dead copper, pour order 273): 1205.27,537.6 1207.27,539.6 1915.27,539.6 2149.27,616.11 2149.27,1148.6 2437.9,1148.6 2437.9,-1.4 1205.27,-1.4
12V_PRI on Layer 3 "NONET_L-01_P-001" (solid, remove dead copper, pour order 337): 4868.38,1239.6 4873.47,1244.68 4913.38,1244.68 4913.38,1177.77 4905.46,1169.84 4868.38,1169.84
3V3_PRI on Layer 3 "NONET_L-01_P-001" (solid, remove dead copper, pour order 420): 3048,4187.6 3123.27,4187.6 3123.27,4142.6 3048,4142.6
PGND on Layer 3 "NONET_L-01_P-001" (solid, remove dead copper, pour order 423): 4614.27,4887 5636,4887 5636,4348.6 4614.27,4348.6
SW_A on Layer 3 "NONET_L-01_P-001" (solid, remove dead copper, pour order 67): 6677.27,3743.97 7130,3743.97 7130,3954.75 7177.12,4025.86 7217.82,4024.01 7276.27,4055.6 7276.27,4082.46 7189.76,4156 6677.27,4156
SGND on Layer 3 "NONET_L-01_P-001" (solid, remove dead copper, pour order 44): 8371.73,4019.6 8371.73,3680.25 9598.97,3680.25 9605,3685 9628,3685 9705.01,3596.85 9705.01,3081 10024.47,3081 10024.47,3398.99 9523.86,3899.6 8537.77,3899.6 8505.01,3916.93 8505.01,4019.43
SGND on Layer 3 "NONET_L-01_P-001" (solid, remove dead copper, pour order 55): 19 vertices, not listed, extent 8367.27,0 10621,1313
TTPLPFC_SW2 on Layer 3 "NONET_L-01_P-001" (solid, remove dead copper, pour order 8): 4897,2952 4253.62,2952 4253.62,2576.59 4897,2576.59
IPRI_SENSE on Layer 3 "NONET_L-01_P-001" (solid, remove dead copper, pour order 91): 4859.24,3984.6 3483.19,3984.6 3483.19,3130.32 3600.25,3130.32 3600.25,1902.98 3361.27,1902.98 3361.27,1283.6 3385.37,1283.6 3856.52,765.03 4723.89,765.03 4723.89,1382.15 4413.38,1382.15 4413.38,3446.51 4861.13,3452.33
TTPLPFC_SW1 on Layer 3 "NONET_L-01_P-001" (solid, remove dead copper, pour order 43): 4885.99,1910.15 4319.61,1910.15 4319.61,1629.63 4472.51,1476.74 4885.99,1476.74
SW_C on Layer 3 "Inner 4-HS_GND_C" (solid, remove dead copper, pour order 45): 18 vertices, not listed, extent 8372.58,2997 10581.4,4385.6
SW_D on Layer 3 "NONET_L-01_P-001" (solid, remove dead copper, pour order 54): 9731,1489 10127.31,1489 10127.31,1014.63 9825.66,1014.63 9342.63,531.6 8557.21,531.6 8473.13,447.52 8371.26,447.52 8371.26,683.95 8607.11,762 9347.81,762 9731,1145.19
SW_A_XFMR on Layer 3 "NONET_L-01_P-001" (solid, remove dead copper, pour order 152): 7055.24,2595.6 7055.24,2946 6564,2946 6564,2665.6 6753.27,2665.6 6823.27,2595.6
SW_C_XFMR on Layer 3 "NONET_L-01_P-001" (solid, remove dead copper, pour order 512): 9802,2748.59 9802,2465 9524.38,2465 9524.38,2748.59
SW_C_RES on Layer 3 "NONET_L-01_P-001" (solid, remove dead copper, pour order 435): 10322.71,2593 10322.71,2456.6 9915,2456.6 9915,2593
AC_N_EMI on Layer 3 "NONET_L-01_P-001" (solid, remove dead copper, pour order 117): 1081.61,2228.01 1683.27,2228.01 1683.27,806.6 1081.61,806.6
AC_N_CON on Layer 3 "NONET_L-01_P-001" (solid, remove dead copper, pour order 95): 1325.74,5030.6 1325.74,4848.22 1049.27,4848.22 1049.27,3322.25 1586.21,2912.11 1586.21,2562.6 1081.4,2562.6 622.27,3037.88 622.27,4488.6 422.27,4688.6 422.27,5030.6
AC_L_CON on Layer 3 "NONET_L-01_P-001" (solid, remove dead copper, pour order 92): -5.86,5275 -9.86,4817.46 32.27,4817.46 28.27,4231.6 559.27,4231.6 562.27,4234.6 562.27,4464.6 561.27,4464.6 251.27,4774.6 251.27,5275
AC_L_F on Layer 3 "NONET_L-01_P-001" (solid, remove dead copper, pour order 93): 20.27,4148.6 562.27,4148.6 562.27,3006.6 708.14,2826.46 708.14,2563.6 20.27,2563.6
AC_L_EMI on Layer 3 "NONET_L-01_P-001" (solid, remove dead copper, pour order 102): -3.54,2252.6 812.27,2252.6 812.27,823.6 -3.54,823.6
3V3_PRI on Layer 5 "NONET_L-01_P-001" (solid, remove dead copper, pour order 140): 29 vertices, not listed, extent 4909.42,10.37 8216.27,4271.86
DCLINK on Layer 5 "NONET_L-01_P-001" (solid, pour order 517): 6035.8,113 6072.8,113 6072.8,92 6035.8,92
SGND on Layer 5 "NONET_L-01_P-001" (solid, remove dead copper, pour order 162): 9388.27,964.6 9388.27,1623.02 9442.91,1677.67 10670,1677.67 10670,964.6
IPRI_SENSE on Layer 5 "NONET_L-01_P-001" (solid, remove dead copper, pour order 146): 2034.27,4427.6 4846.46,4427.6 4847.25,3702.13 5301.18,3058.87 5301.18,2115.62 4463.12,834.6 2678.27,834.6 2678.27,1909.6 3570.24,1909.6 3570.24,3115.2 3180.27,3115.2 3180.27,3757.46 2034.27,3757.46
VBATT_F on Layer 5 "NONET_L-01_P-001" (solid, remove dead copper, pour order 158): 9383.24,3702.94 9383.24,2788.72 10670,2788.56 10670,3267.13 10644.34,3292.79 10592.84,3292.79 9628.27,3292.79 9628.27,3706.26
12V_SW on Layer 5 "NONET_L-01_P-001" (solid, remove dead copper, pour order 131): 29 vertices, not listed, extent 5623.18,407 7957,4412.6
5V_PRI on Layer 5 "NONET_L-01_P-001" (solid, remove dead copper, pour order 119): 18 vertices, not listed, extent 5472.33,171.1 6011.27,4230.6
EARTH on Layer 5 "NONET_L-01_P-001" (solid, remove dead copper, pour order 116): 0,4781.6 1915.54,4781.6 1915.54,1248.74 1915.54,753.6 4009.27,753.6 4009.27,43.6 0,43.6 0,598.71 0,1248.74 0,1431.21
12V_SW on Layer 5 "NONET_L-01_P-001" (solid, remove dead copper, pour order 112): 5645,4447.1 7943.27,4447.1 7943.27,3979.39 7943.27,3704.6 7828.27,3704.6 7383,3704.6 7383,4079 7296,4166 5645,4166
DCLINK on Layer 5 "NONET_L-01_P-001" (solid, remove dead copper, pour order 118): 5980,4157 5980,3497.56 6250.71,3293.35 6579.02,3293.35 6821.57,3472.47 7340.27,3472.47 7340.27,4157
PGND on Layer 5 "NONET_L-01_P-001" (solid, remove dead copper, pour order 394): 6204,701 6676.34,702.99 6741,783.6 7453.99,783.6 7568.27,783.6 7568.27,287 7112.67,287 7052.5,366 6637.71,366 6519.14,201.6 6204,201.6
12V_PRI on Layer 5 "NONET_L-01_P-001" (solid, remove dead copper, pour order 139): 19 vertices, not listed, extent 5208.9,174.6 5738.27,4276
AC_N on Layer 5 "NONET_L-01_P-001" (solid, remove dead copper, pour order 169): 3158.27,3134.6 2663.36,3134.6 2663.36,1935.47 2663.36,790.18 2246.82,790.18 1972.27,1064.73 1972.27,3738.2 3158.27,3738.2
5V_L_C on Layer 5 "NONET_L-01_P-001" (solid, remove dead copper, pour order 47): 8372.13,4016.11 8372.13,3652.12 8552.54,3652.12 8552.54,3827.6 8527.63,3827.6 8502.01,3870.7 8502.01,4013.74
5V_H_C on Layer 5 "NONET_L-01_P-001" (solid, remove dead copper, pour order 71): 8372.35,4427.52 8372.35,4063.52 8694.89,4063.52 8694.89,4427.52
SW_A_XFMR on Layer 5 "NONET_L-01_P-001" (solid, remove dead copper, pour order 350): 7052.51,2598.29 7052.51,2948.69 6561.27,2948.69 6561.27,2668.29 6750.54,2668.29 6820.54,2598.29
VBATT on Layer 5 "NONET_L-01_P-001" (solid, remove dead copper, pour order 358): 10449.1,1751.1 11034.44,1751.1 11034.44,2465.6 10449.1,2465.6
SW_D_RES on Layer 5 "NONET_L-01_P-001" (solid, remove dead copper, pour order 365): 9705.09,1957 10221.72,1957 10221.72,1819.6 9929.57,1819.6 9783.64,1691.74 9707.78,1692.61
SW_C_XFMR on Layer 5 "NONET_L-01_P-001" (solid, remove dead copper, pour order 421): 9805.4,2458 9527.33,2458 9527.33,2709 9804.89,2709
SW_C_RES on Layer 5 "NONET_L-01_P-001" (solid, remove dead copper, pour order 364): 10329,2454 9911.33,2454 9911.33,2601 10328.7,2601
DCLINK on Layer 6 "NONET_L-01_P-001" (solid, pour order 518): 6035.8,113 6072.8,113 6072.8,92 6035.8,92
SGND on Layer 6 "NONET_L-01_P-001" (solid, remove dead copper, pour order 129): 8370.73,4451.6 8370.72,0 10670.27,0 10670.27,4451.6
DCLINK on Layer 6 "NONET_L-01_P-001" (solid, remove dead copper, pour order 357): 22 vertices, not listed, extent 2716.27,0 4594.27,3850.92
IPRI_SENSE on Layer 6 "NONET_L-01_P-001" (solid, remove dead copper, pour order 111): 4730.17,3433.32 4398.81,3433.32 4398.81,2999.91 4897.04,2999.91 4932.27,3112.34 4932.27,3263.63
3V3_PRI on Layer 6 "NONET_L-01_P-001" (solid, remove dead copper, pour order 338): 6367,3256.1 5150.22,3256.1 4931.27,3256.1 4931.27,2902.6 4931.27,1140.71 5097.64,974.33 5097.64,636.23 5255.8,636.23 5255.8,1529.99 5173.93,1611.85 5173.93,1990.43 5173.93,2599.21 5543.7,2968.98 6367,2968.98
DCLINK on Layer 6 "NONET_L-01_P-001" (solid, remove dead copper, pour order 138): 5966,4164.73 5966,3358.6 7306,3358.6 7306,4164.73
5V_PRI on Layer 6 "NONET_L-01_P-001" (solid, remove dead copper, pour order 141): 5433,4439 7877,4439 7877,3695.56 7325,3695.56 7325,4186.6 5809.87,4186.6 5630.27,4007 5630.27,3271 5113,3271 5113,4119
PGND on Layer 6 "NONET_L-01_P-001" (solid, remove dead copper, pour order 201): 6243.56,783.6 7272,783.6 7568.27,686.73 7568.27,301.03 7140.05,301.03 7030.48,410.6 6719.22,410.6 6510.22,201.6 6243.56,201.6 6243.56,345.71
VBATT_F on Layer 6 "NONET_L-01_P-001" (solid, remove dead copper, pour order 171): 9383.24,3649.29 9383.24,2788.72 10670,2788.56 10670,3202.91 10554.46,3202.91 10498.04,3146.48 9723.54,3146.48 9628.27,3241.75 9628.27,3652.61
AC_N on Layer 6 "NONET_L-01_P-001" (solid, remove dead copper, pour order 208): 3110.53,1904.98 3121.27,1894.24 3121.27,756.6 2523.37,756.6 2430.51,849.46 2430.51,1905.61
5V_PRI on Layer 6 "NONET_L-01_P-001" (solid, remove dead copper, pour order 354): 23 vertices, not listed, extent 5266,328.86 7916.52,2174.11
AC_L on Layer 6 "NONET_L-01_P-001" (solid, remove dead copper, pour order 144): 262.8,682.05 1741.19,683.25 1831.8,792.89 1831.8,2168.31 2294.53,2670.31 2502.48,2670.31 2502.48,2427.31 2409.8,2295.6 2409.8,835.07 2705.3,539.57 3459.8,540.18 3459.8,1.31 262.8,1.31
SW_A_XFMR on Layer 6 "NONET_L-01_P-001" (solid, remove dead copper, pour order 367): 7052.51,2596.29 7052.51,2946.69 6561.27,2946.69 6561.27,2666.29 6750.54,2666.29 6820.54,2596.29
VBATT on Layer 6 "NONET_L-01_P-001" (solid, remove dead copper, pour order 368): 10452.27,1751.1 11037.61,1751.1 11037.61,2465.6 10452.27,2465.6
SW_D_RES on Layer 6 "NONET_L-01_P-001" (solid, remove dead copper, pour order 24): 9705.08,1957.06 10221.71,1957.06 10221.71,1819.66 9929.57,1819.66 9783.63,1691.8 9707.77,1692.67
SW_C_XFMR on Layer 6 "NONET_L-01_P-001" (solid, remove dead copper, pour order 9): 9838.38,2451.16 9553,2451.16 9553,2749.16 9837.77,2749.16
IPRI_SENSE on Layer 6 "NONET_L-01_P-001" (solid, remove dead copper, pour order 58): 4881.23,2396.92 4353.87,2395.5 4314.85,2356.48 4314.85,1931.6 4881.23,1931.6
DCLINK on Layer 4 "NONET_L-01_P-001" (solid, remove dead copper, pour order 159): 1761.27,4427.6 1761.27,2722.6 3135.27,2722.6 3135.27,767.63 3336.39,566.5 3336.39,4.91 7550.27,-2.8 7550.27,4427.6
VBATT_F on Layer 4 "NONET_L-01_P-001" (solid, remove dead copper, pour order 101): 8370.73,4451.6 8370.72,0 10670.27,0 10670.27,4451.6
AC_N on Layer 4 "NONET_L-01_P-001" (solid, remove dead copper, pour order 316): 3110.53,1904.98 3121.27,1894.24 3121.27,674.6 2605.37,674.6 2430.51,849.46 2430.51,1905.61
AC_L on Layer 4 "NONET_L-01_P-001" (solid, remove dead copper, pour order 143): 256.27,679.05 1734.42,680.25 1825.27,790.18 1825.27,2667.6 2495.95,2667.6 2495.95,2376 2403.27,2376 2403.27,855.6 2895.19,363.67 3453.27,364.13 3453.27,-1.4 256.27,-1.4
5V_L_D on Layer 4 "NONET_L-01_P-001" (solid, remove dead copper, pour order 73): 8387.61,246.66 8387.61,19.65 8506,19.65 8506,246.66
SW_A_XFMR on Layer 4 "NONET_L-01_P-001" (solid, remove dead copper, pour order 84): 7054.51,2597.29 7054.51,2947.69 6563.27,2947.69 6563.27,2667.29 6752.54,2667.29 6822.54,2597.29
DCLINK on Layer 4 "NONET_L-01_P-001" (solid, remove dead copper, pour order 351): 3958,4143.27 3958,4887 4731,4887 4731,4143.27
5V_H_D on Layer 4 "NONET_L-01_P-001" (solid, remove dead copper, pour order 59): 8415.39,683.01 8415.39,447.52 8545.26,447.52 8545.26,537.6 8545.26,683.01
AC_N_EMI on Layer 4 "NONET_L-01_P-001" (solid, remove dead copper, pour order 346): 1077.61,2228.18 1679.27,2228.18 1679.27,806.76 1077.61,806.76
AC_N_CON on Layer 4 "NONET_L-01_P-001" (solid, remove dead copper, pour order 319): 1325.74,5033.6 1325.74,4851.22 1049.27,4851.22 1049.27,3325.25 1586.21,2915.11 1586.21,2565.6 1081.4,2565.6 622.27,3040.88 622.27,4491.6 422.27,4691.6 422.27,5033.6
AC_L_CON on Layer 4 "NONET_L-01_P-001" (solid, remove dead copper, pour order 317): -5.89,5271 -9.83,4820.46 32.27,4820.46 28.27,4234.6 559.27,4234.6 562.27,4237.6 562.27,4467.6 561.27,4467.6 251.27,4777.6 251.27,5271
AC_L_F on Layer 4 "NONET_L-01_P-001" (solid, remove dead copper, pour order 318): 20.27,4151.6 562.27,4151.6 562.27,3009.6 708.14,2829.46 708.14,2566.6 20.27,2566.6
AC_L_EMI on Layer 4 "NONET_L-01_P-001" (solid, remove dead copper, pour order 320): -7.53,2252.76 808.27,2252.76 808.27,823.76 -7.53,823.76
DCLINK on Layer 7 "NONET_L-01_P-001" (solid, pour order 519): 6035.5,113 6072.5,113 6072.5,92 6035.5,92
SGND on Layer 7 "NONET_L-01_P-001" (solid, remove dead copper, pour order 369): 9388.27,964.6 9388.27,1623.02 9442.91,1677.67 10619.04,1677.67 10619.04,1323 10555,1323 10535,1303 10336.28,1303 10283.02,1249.74 10283.02,964.6
DCLINK on Layer 7 "NONET_L-01_P-001" (solid, remove dead copper, pour order 332): 4594.27,3849.6 3866.27,3849.6 2716.27,3851.16 2716.27,3118.88 3598.27,3118.88 3598.27,2345.97 4302.27,2345.97 4380,2384.86 4380,2492.41 4254,2626.44 4254,2953.99 4398.92,3098.9 4594.27,3098.9
SGND on Layer 7 "NONET_L-01_P-001" (solid, pour order 303): 10349.63,1289.63 10302,1242 10302,1091 10330,1063 10626,1063 10665,1102 10665,1244 10620.43,1288.57 10620.43,1311 10566.92,1311 10545.55,1289.63
VBATT_F on Layer 7 "NONET_L-01_P-001" (solid, remove dead copper, pour order 370): 9383.24,3702.94 9383.24,2788.72 10670,2788.56 10670,3267.13 10644.34,3292.79 10592.84,3292.79 9628.27,3292.79 9628.27,3706.26
SGND on Layer 7 "NONET_L-01_P-001" (solid, pour order 137): 9739.85,3325.77 9684.85,3270.77 9684.85,3119.77 9712.85,3091.77 10008.85,3091.77 10047.85,3130.77 10047.85,3272.77 9995.85,3324.77
PGND on Layer 7 "NONET_L-01_P-001" (solid, pour order 72): 6296.85,4120.77 6241.85,4065.77 6241.85,3914.77 6269.85,3886.77 6565.85,3886.77 6604.85,3925.77 6604.85,4067.77 6552.85,4119.77
TTPLPFC_SW2 on Layer 7 "NONET_L-01_P-001" (solid, remove dead copper, pour order 312): 4769,2968.98 4289.29,2968.98 4289.29,2649.71 4403.42,2535.57 4769,2535.57
DCLINK on Layer 7 "NONET_L-01_P-001" (solid, remove dead copper, pour order 361): 5973,4169.61 5973,3363.47 7342.27,3363.47 7342.27,4169.61
TTPLPFC_SW1 on Layer 7 "NONET_L-01_P-001" (solid, pour order 501): 4321,1895 4680,1895 4733,1842 4733,1524 4689,1480 4475,1480 4321,1634
SW_A on Layer 7 "NONET_L-01_P-001" (solid, pour order 308): 6761,4110 7092,4110 7132,4070 7132,3916 7101,3885 6802,3885 6747,3940 6747,4096
SW_B on Layer 7 "NONET_L-01_P-001" (solid, pour order 499): 6536,208 6674,346 7067,346 7110,303 7110,143 7077,110 6574,110 6536,148
PGND on Layer 7 "NONET_L-01_P-001" (solid, remove dead copper, pour order 356): 6243.56,783.6 7453.99,783.6 7568.27,783.6 7568.27,318 7522,318 7461,401 6709.62,401 6518.22,209.6 6243.56,209.6 6243.56,345.71
SW_C on Layer 7 "NONET_L-01_P-001" (solid, pour order 321): 10233.73,3402.52 10178.73,3347.52 10178.73,3152.27 10242,3089 10423.21,3089 10541.73,3207.52 10541.73,3349.52 10489.73,3401.52
SW_D on Layer 7 "NONET_L-01_P-001" (solid, pour order 331): 9878.22,1380.22 9809,1311 9809,1127 9837,1099 10133,1099 10172,1138 10172,1280 10072.54,1379.46
AC_N on Layer 7 "NONET_L-01_P-001" (solid, remove dead copper, pour order 422): 3110.53,1904.98 3121.27,1894.24 3121.27,456 2454,456 2454,1905.59
PGND on Layer 7 "NONET_L-01_P-001" (solid, pour order 500): 7554,279 7535,298 7522.41,298 7464.41,376 7140,376 7140,108 7149,99 7554,99
3V3_PRI on Layer 7 "NONET_L-01_P-001" (solid, remove dead copper, pour order 341): 2918.27,4137.6 3234,4137.6 3234,4452.6 3028.27,4452.6 3028.27,5052.6 2548.27,5052.6 2553.27,5047.6 2553.27,4577.6 2918.27,4577.6
12V_SW on Layer 7 "NONET_L-01_P-001" (solid, remove dead copper, pour order 334): 5613.27,4417.6 5713.27,4417.6 5713.27,4352.6 5613.27,4352.6
IPRI_SENSE on Layer 7 "NONET_L-01_P-001" (solid, remove dead copper, pour order 371): 3621,2343.88 3621,1892 3128,1892 3128,1150 3621,1150 3939,832 4630,832 4667,869 4667,1371 4562,1371 4308,1625 4308,2252 4341,2252 4341,2343.88
SW_A_XFMR on Layer 7 "NONET_L-01_P-001" (solid, remove dead copper, pour order 372): 7054.51,2600.29 7054.51,2950.69 6563.27,2950.69 6563.27,2670.29 6752.54,2670.29 6822.54,2600.29
VBATT on Layer 7 "NONET_L-01_P-001" (solid, remove dead copper, pour order 450): 10445.94,1754.26 11031.28,1754.26 11031.28,2468.76 10445.94,2468.76
SW_D_RES on Layer 7 "NONET_L-01_P-001" (solid, remove dead copper, pour order 456): 9708.08,1960.06 10224.71,1960.06 10224.71,1822.66 9932.57,1822.66 9786.63,1694.8 9710.77,1695.67
SW_C_XFMR on Layer 7 "NONET_L-01_P-001" (solid, remove dead copper, pour order 493): 9803.32,2465 9531.96,2465 9531.96,2719.02 9802.8,2719.02
AC_N_Re on Layer 7 "NONET_L-01_P-001" (solid, remove dead copper, pour order 353): 1198.21,537.6 1200.21,539.6 1908.21,539.6 2142.21,616.11 2142.21,1148.6 2430.84,1148.6 2430.84,-1.4 1198.21,-1.4
AC_N on Layer 7 "NONET_L-01_P-001" (solid, pour order 478): 3036,742 4981,742 4981,28 4897,28 4468,457 3036,457
AC_L on Layer 7 "NONET_L-01_P-001" (solid, pour order 477): 3195,337 4544,337 4703,178 4703,28 4553,28 3195,28
SW_C_RES on Layer 7 "NONET_L-01_P-001" (solid, remove dead copper, pour order 460): 10322.04,2457 9912.03,2457 9912.03,2595 10321.76,2595
ISO_ETAS_GND on Layer 7 "NONET_L-01_P-001" (solid, remove dead copper, pour order 336): 1923.27,5102.6 1928.27,5107.6 2443.27,5107.6 2443.27,4532.6 2418.27,4507.6 1923.27,4507.6
5V_H_B on Layer 2 "NONET_L-01_P-001" (solid, pour order 520): 6106,298 6106,154 6167,93 6194,93 6194,139 6150,183 6150,298
DCLINK on Layer 2 "NONET_L-01_P-001" (solid, pour order 515): 6035.8,113 6072.8,113 6072.8,92 6035.8,92
5V_H_PFC_1 on Layer 2 "NONET_L-01_P-001" (solid, pour order 458): 4480,1573 4751,1573 4818,1640 4818,1699 4833,1714 4834,1713 4860,1713 4872,1701 4872,1569 4809,1506 4480,1506
5V_H_PFC_2 on Layer 2 "NONET_L-01_P-001" (solid, pour order 491): 4272,2944 4861,2944 4861,2588 4271,2588
IPRI_SENSE on Layer 2 "NONET_L-01_P-001" (solid, remove dead copper, pour order 5): 27 vertices, not listed, extent 2706,765.03 5279.27,3984.6
5V_H_D on Layer 2 "NONET_L-01_P-001" (solid, pour order 457): 8485,631 8405,631 8384,610 8384,473 8410,447 8459,447 8459,480 8438,480 8426,492 8426,562 8441,577 8459,577 8485,603
ISO_12V_H_PFC_1 on Layer 2 "NONET_L-01_P-001" (solid, pour order 443): 4472,1847 4510,1847 4666,1691 4666,1644 4592,1644 4472,1764
NetL4_2 on Layer 2 "NONET_L-01_P-001" (solid, pour order 495): 6807,3998 6807,3896 6866,3837 7044,3837 7044,3887 7017,3914 6945,3914 6861,3998
NetL8_2 on Layer 2 "NONET_L-01_P-001" (solid, pour order 482): 10148.36,3301 10206,3301 10206,3092 10225,3073 10225,3020 10166,3020 10148.36,3037.64
AC_N on Layer 2 "NONET_L-01_P-001" (solid, remove dead copper, pour order 322): 3158.27,3134.6 2663.36,3134.6 2663.36,1935.47 2663.36,790.18 2463.68,790.18 2090.27,1163.6 2090.27,3738.2 3158.27,3738.2
ISO_12V_H_A on Layer 2 "NONET_L-01_P-001" (solid, pour order 470): 6599,3659 6656,3659 6656,3600 6599,3600
5V_L_D on Layer 2 "NONET_L-01_P-001" (solid, pour order 468): 10078,676 10146,676 10146,719 10078,719
5V_L_D on Layer 2 "NONET_L-01_P-001" (solid, pour order 467): 9341,336 9341,268 9384,268 9384,336
SGND on Layer 2 "NONET_L-01_P-001" (solid, pour order 463): 8410,3801 8410,3744 8418,3736 8503,3736 8503,3760 8488,3775 8458,3775 8432,3801
SW_A_XFMR on Layer 2 "NONET_L-01_P-001" (solid, remove dead copper, pour order 352): 7056.61,2594.69 7056.61,2945.08 6565.37,2945.08 6565.37,2664.69 6754.64,2664.69 6824.64,2594.69
VBATT on Layer 2 "NONET_L-01_P-001" (solid, remove dead copper, pour order 359): 10445.94,1751.1 11031.28,1751.1 11031.28,2465.6 10445.94,2465.6
SW_D_RES on Layer 2 "NONET_L-01_P-001" (solid, remove dead copper, pour order 363): 9705.09,1957 10221.72,1957 10221.72,1819.6 9929.57,1819.6 9783.64,1691.74 9707.78,1692.61
SW_C_XFMR on Layer 2 "NONET_L-01_P-001" (solid, remove dead copper, pour order 416): 9808.29,2447 9530.23,2447 9530.23,2745 9807.68,2745
NetL7_2 on Layer 2 "NONET_L-01_P-001" (solid, pour order 412): 9939,3047 9808,3047 9716,3139 9716,3329 9656,3329 9656,3116 9769,3003 9939.69,3003
NetL10_2 on Layer 2 "NONET_L-01_P-001" (solid, pour order 405): 9982,1463 9983,1462 10042,1462 10042,1432 10152,1322 10152,1181 10072,1181 10072,1305 9982,1395
5V_L_A on Layer 2 "NONET_L-01_P-001" (solid, pour order 384): 6546,4046 6603,4046 6606,4043 6606,3796 6596,3786 6489,3786 6469,3806 6469,3880 6527,3938 6527,4025.27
